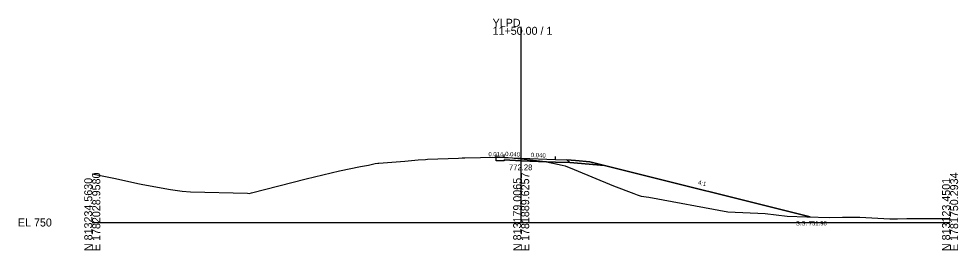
# Model space of a CAD drawing. Extents: x -26 to 353, y -10 to 9080.
# Drawn here: x -25.7 to 302.8, y 1490.3 to 1571.2 of the extents above; entities that cross this region are included whole.
import ezdxf

# ---------------------------------------------------------------- set-up
doc = ezdxf.new("R2010")
doc.units = 0
for name, color, linetype in [('Exist Cross Section Cell', 7, 'Continuous'), ('Exist XS Center Line Elevation Label', 7, 'Continuous'), ('Exist XS Ground Line', 7, 'Continuous'), ('Prop XS Dump Level', 7, 'Continuous'), ('Prop XS Earthwork Shape', 7, 'Continuous'), ('Prop XS EOT Tick Mark', 7, 'Continuous'), ('Prop XS Finish Grade', 7, 'Continuous'), ('Prop XS Finish Grade Earthwork', 7, 'Continuous'), ('Prop XS Finish Grade Paved Shoulder', 7, 'Continuous'), ('Prop XS Finish Grade Pavement', 7, 'Continuous'), ('Prop XS Pvmt Edge Slope', 7, 'Continuous'), ('Prop XS SE Text', 7, 'Continuous'), ('Prop XS Side Slope Text', 7, 'Continuous'), ('Prop XS SS Elevation Text', 7, 'Continuous'), ('Prop XS Subgrade Earthwork', 7, 'Continuous'), ('Scratch_Level_3', 7, 'Continuous')]:
    doc.layers.add(name, color=color, linetype=linetype)

msp = doc.modelspace()

# ---------------------------------------------------------------- linework, layer by layer
at = {"layer": 'Exist Cross Section Cell'}
for p, q in [((150, 1500), (150, 1568.44)), ((0, 1500), (150, 1500)), ((150, 1500), (300, 1500))]:
    msp.add_line(p, q, dxfattribs=at)
at = {"layer": 'Exist XS Ground Line'}
for p, q in [((101.7, 1520.91), (109.37, 1521.44)), ((109.37, 1521.44), (113.95, 1521.86)), ((113.95, 1521.86), (116.52, 1522.06)), ((116.52, 1522.06), (117.28, 1522.12)), ((117.28, 1522.12), (128.05, 1522.51)), ((128.05, 1522.51), (129.33, 1522.57)), ((129.33, 1522.57), (130.35, 1522.59)), ((130.35, 1522.59), (141.26, 1522.81)), ((141.26, 1522.81), (145.49, 1522.77)), ((145.49, 1522.77), (146.92, 1522.62)), ((146.92, 1522.62), (147.58, 1522.55)), ((147.58, 1522.55), (150, 1522.28)), ((150, 1522.28), (158.54, 1521.33)), ((158.54, 1521.33), (164.39, 1520.03)), ((80.62, 1516.66), (86.48, 1518.01)), ((86.48, 1518.01), (93.85, 1519.53)), ((93.85, 1519.53), (96.62, 1520.1)), ((96.62, 1520.1), (98.94, 1520.62)), ((98.94, 1520.62), (99.85, 1520.77)), ((99.85, 1520.77), (100.27, 1520.8)), ((100.27, 1520.8), (101.7, 1520.91)), ((164.39, 1520.03), (165.4, 1519.81)), ((165.4, 1519.81), (168.48, 1518.58)), ((168.48, 1518.58), (182.31, 1512.86)), ((0, 1516.97), (8.12, 1515.39)), ((8.12, 1515.39), (11.76, 1514.56)), ((11.76, 1514.56), (16.47, 1513.54)), ((55.68, 1510.42), (74.86, 1515.3)), ((74.86, 1515.3), (80.62, 1516.66)), ((16.47, 1513.54), (17.69, 1513.33)), ((17.69, 1513.33), (27.38, 1511.52)), ((27.38, 1511.52), (31.48, 1510.96)), ((182.31, 1512.86), (189.4, 1510.11)), ((31.48, 1510.96), (34.39, 1510.68)), ((34.39, 1510.68), (54.27, 1510.24)), ((54.27, 1510.24), (54.83, 1510.19)), ((54.83, 1510.19), (55.68, 1510.42)), ((189.4, 1510.11), (190.55, 1509.63)), ((190.55, 1509.63), (191.99, 1509.16)), ((191.99, 1509.16), (194.7, 1508.86)), ((194.7, 1508.86), (222.32, 1503.77)), ((222.32, 1503.77), (235.33, 1503.2)), ((235.33, 1503.2), (243.06, 1502.21)), ((243.06, 1502.21), (249.91, 1502.01)), ((249.91, 1502.01), (257.94, 1501.78)), ((257.94, 1501.78), (262.42, 1501.9)), ((262.42, 1501.9), (268.45, 1501.92)), ((268.45, 1501.92), (278.95, 1501.32)), ((278.95, 1501.32), (281.55, 1501.27)), ((281.55, 1501.27), (284.84, 1501.36)), ((284.84, 1501.36), (300, 1501.37))]:
    msp.add_line(p, q, dxfattribs=at)
at = {"layer": 'Prop XS Dump Level'}
for p, q in [((144, 1522.78), (150, 1522.54)), ((150, 1522.54), (162, 1522.06))]:
    msp.add_line(p, q, dxfattribs=at)
at = {"layer": 'Prop XS Earthwork Shape'}
for points in [[(141.26, 1521.56), (141.26, 1522.81), (145.49, 1522.77), (146.92, 1522.62), (147.58, 1522.55), (150, 1522.28), (158.54, 1521.33), (158.82, 1521.27), (149.96, 1521.62), (144, 1521.86), (144, 1521.53)], [(249.91, 1502.01), (251.11, 1501.98), (179.17, 1519.96), (166.96, 1520.94), (161.96, 1521.14), (158.82, 1521.27), (164.39, 1520.03), (165.4, 1519.81), (168.48, 1518.58), (182.31, 1512.86), (189.4, 1510.11), (190.55, 1509.63), (191.99, 1509.16), (194.7, 1508.86), (222.32, 1503.77), (235.33, 1503.2), (243.06, 1502.21)]]:
    msp.add_lwpolyline(points, close=True, dxfattribs=at)
at = {"layer": 'Prop XS EOT Tick Mark'}
for p, q in [((141.26, 1522.81), (141.26, 1523.81)), ((144, 1522.78), (144, 1523.78)), ((162, 1522.06), (162, 1523.06))]:
    msp.add_line(p, q, dxfattribs=at)
at = {"layer": 'Prop XS Finish Grade'}
for p, q in [((166, 1521.9), (169, 1521.66)), ((169, 1521.66), (174, 1521.26)), ((174, 1521.26), (179.17, 1519.96))]:
    msp.add_line(p, q, dxfattribs=at)
at = {"layer": 'Prop XS Finish Grade Earthwork'}
msp.add_line((179.17, 1519.96), (251.11, 1501.98), dxfattribs=at)
at = {"layer": 'Prop XS Finish Grade Paved Shoulder'}
for p, q in [((144, 1522.78), (141.26, 1522.81)), ((162, 1522.06), (166, 1521.9))]:
    msp.add_line(p, q, dxfattribs=at)
at = {"layer": 'Prop XS Finish Grade Pavement'}
for p, q in [((144, 1522.78), (150, 1522.54)), ((150, 1522.54), (162, 1522.06))]:
    msp.add_line(p, q, dxfattribs=at)
at = {"layer": 'Prop XS Pvmt Edge Slope'}
msp.add_line((166, 1521.9), (166.96, 1520.94), dxfattribs=at)
at = {"layer": 'Prop XS Subgrade Earthwork'}
for p, q in [((141.26, 1521.56), (141.26, 1522.81)), ((144, 1521.53), (141.26, 1521.56)), ((144, 1521.86), (149.96, 1521.62)), ((144, 1521.53), (144, 1521.86)), ((149.96, 1521.62), (161.96, 1521.14)), ((161.96, 1521.14), (166.96, 1520.94)), ((166.96, 1520.94), (179.17, 1519.96))]:
    msp.add_line(p, q, dxfattribs=at)
at = {"layer": 'Scratch_Level_3'}
for p, q in [((169, 1521.66), (166, 1521.9)), ((166, 1521.9), (166.96, 1520.94)), ((174, 1521.26), (169, 1521.66)), ((179.17, 1519.96), (174, 1521.26)), ((166.96, 1520.94), (179.17, 1519.96))]:
    msp.add_line(p, q, dxfattribs=at)

# ---------------------------------------------------------------- texts
at = {"layer": 'Exist Cross Section Cell'}
for s, p in [('YLPD', (140, 1568.44)), ('11+50.00 / 1', (140, 1565.64)), ('EL 750', (-26, 1498.6))]:
    msp.add_text(s, height=2.8, dxfattribs=at).set_placement(p)
for s, p in [('N 813234.5630', (0, 1490)), ('E 1782028.9580', (2.8, 1490)), ('N 813179.0065', (150, 1490)), ('E 1781889.6257', (152.8, 1490)), ('N 813123.4501', (300, 1490)), ('E 1781750.2934', (302.8, 1490))]:
    msp.add_text(s, height=2.8, rotation=90, dxfattribs=at).set_placement(p)
at = {"layer": 'Exist XS Center Line Elevation Label'}
msp.add_text('772.28', height=2, dxfattribs=at).set_placement((145.73, 1518.28))
at = {"layer": 'Prop XS Dump Level'}
msp.add_text('Case4', height=0.04, dxfattribs=at).set_placement((174, 1521.22))
at = {"layer": 'Prop XS SE Text'}
for s, rotation, p in [('0.014', 359.9148, (138.54, 1523.16)), ('0.040', 357.7072, (144.38, 1523.26)), ('0.040', 357.7094, (153.38, 1522.9))]:
    msp.add_text(s, height=1.5, rotation=rotation, dxfattribs=at).set_placement(p)
at = {"layer": 'Prop XS Side Slope Text'}
msp.add_text('4:1', height=1.5, rotation=345.9638, dxfattribs=at).set_placement((211.74, 1513.37))
at = {"layer": 'Prop XS SS Elevation Text'}
msp.add_text('S.S. 751.98', height=1.5, dxfattribs=at).set_placement((246.06, 1498.98))

doc.saveas('drawing.dxf')
